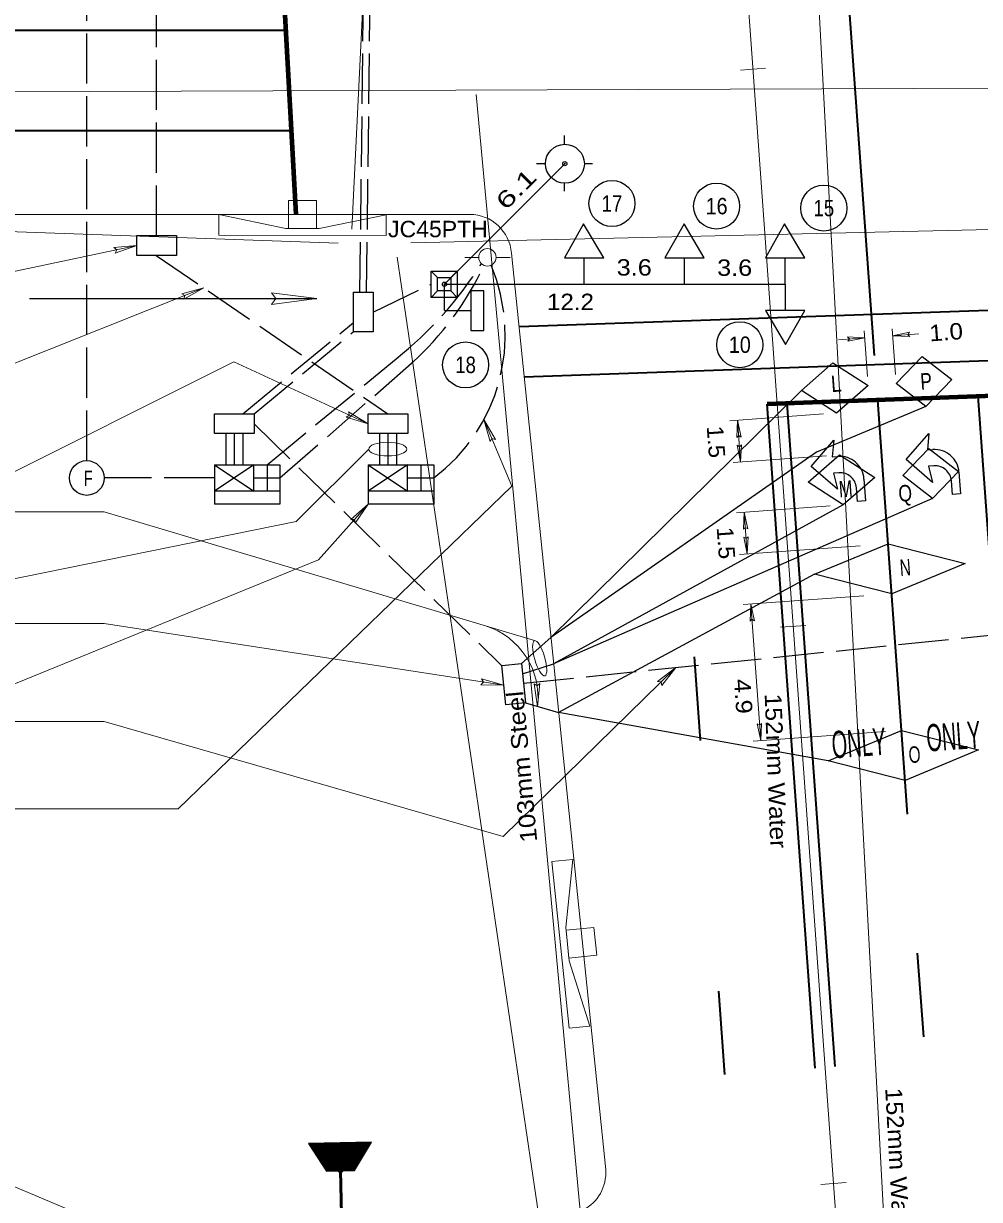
# Model space of a CAD drawing. Extents: x 168203 to 169863, y 223196 to 223870.
# Drawn here: x 168325.25 to 168359.48, y 223583.39 to 223625.5 of the extents above; entities that cross this region are included whole.
import ezdxf
from ezdxf.enums import TextEntityAlignment as Align

# ---------------------------------------------------------------- set-up
doc = ezdxf.new("R2010")
doc.units = 0
doc.header["$LTSCALE"] = 0.3
doc.header["$PDMODE"] = 32
doc.header["$PDSIZE"] = 0.15
doc.linetypes.add('LONG_DASH_SHORT_DASH', pattern=[9.9, 6, -1.2, 1.5, -1.2])
doc.linetypes.add('LONG_DASHED', pattern=[7.5, 6, -1.5])
for name, color, linetype, lineweight in [('1', 7, 'Continuous', 13), ('11', 7, 'Continuous', 13), ('23', 7, 'Continuous', 25), ('3', 7, 'Continuous', 25), ('31', 7, 'Continuous', 25), ('36', 7, 'Continuous', 35), ('5', 7, 'Continuous', 25), ('7', 7, 'Continuous', 25), ('9', 7, 'Continuous', 13)]:
    doc.layers.add(name, color=color, linetype=linetype, lineweight=lineweight)

msp = doc.modelspace()

# ---------------------------------------------------------------- linework, layer by layer
at = {"layer": '1'}
for p, q in [((168355.9956, 223559.8648), (168350.6186, 223634.2675)), ((168350.9207, 223623.8346), (168351.8184, 223623.8995)), ((168298.0344, 223618.6676), (168341.2267, 223618.6675)), ((168341.5495, 223617.1291), (168341.0495, 223617.1291)), ((168342.1745, 223617.1291), (168342.6745, 223617.1291)), ((168342.7229, 223617.2756), (168346.0972, 223584.4572)), ((168352.3629, 223603.8867), (168353.2606, 223603.9516)), ((168280.5516, 223602.5453), (168328.4093, 223582.3863)), ((168353.8048, 223583.9354), (168354.7025, 223584.0002))]:
    msp.add_line(p, q, dxfattribs=at)
for points in [[(168334.737, 223618.1634), (168334.737, 223619.1664), (168335.74, 223619.1664), (168335.74, 223618.1634)], [(168332.2417, 223618.6695), (168332.2401, 223617.9194), (168338.2401, 223617.9068), (168338.2417, 223618.6569), (168335.8406, 223618.1618), (168334.6406, 223618.1644)], [(168344.1749, 223595.4915), (168344.921, 223595.5682), (168344.6691, 223593.1297), (168344.7917, 223591.936), (168345.5347, 223589.5997), (168344.7885, 223589.523)], [(168344.6794, 223593.0358), (168345.6771, 223593.1383), (168345.7797, 223592.1406), (168344.782, 223592.038)]]:
    msp.add_lwpolyline(points, close=True, dxfattribs=at)
msp.add_circle((168341.862, 223617.1291), 0.3125, dxfattribs=at)
for centre, start, end in [((168341.2267, 223617.1675), 4.13349, 90.00005), ((168344.6012, 223584.3492), 297.10142, 4.13349)]:
    msp.add_arc(centre, 1.5, start, end, dxfattribs=at)
at = {"layer": '11'}
for p, q in [((168329.3071, 223617.5491), (168323.7837, 223616.3871)), ((168331.7086, 223616.0342), (168323.7837, 223612.8871)), ((168330.7837, 223597.3871), (168305.2886, 223597.3871))]:
    msp.add_line(p, q, dxfattribs=at)
for points in [[(168328.4908, 223617.4789), (168329.3071, 223617.5491), (168328.5335, 223617.2756), (168328.5909, 223617.3984)], [(168330.916, 223615.8264), (168331.7086, 223616.0342), (168330.9927, 223615.6333), (168331.0284, 223615.7641)], [(168336.8928, 223611.5991), (168337.5893, 223611.1675), (168336.8056, 223611.4104), (168336.925, 223611.4747)], [(168341.9597, 223610.5314), (168341.7389, 223611.3205), (168342.1515, 223610.6113), (168342.0201, 223610.6448)], [(168336.9737, 223607.7476), (168337.5888, 223608.2889), (168337.1289, 223607.6094), (168337.102, 223607.7423)]]:
    msp.add_lwpolyline(points, close=True, dxfattribs=at)
for points in [[(168337.5893, 223611.1675), (168332.7853, 223613.3888), (168323.7837, 223608.8871)], [(168341.7389, 223611.3205), (168342.7329, 223608.9324), (168330.7837, 223597.3871)], [(168337.6116, 223610.2636), (168335.0198, 223607.6653), (168323.7837, 223605.3871)], [(168337.5888, 223608.2889), (168335.8167, 223606.299), (168323.7837, 223601.3871)]]:
    msp.add_lwpolyline(points, dxfattribs=at)
msp.add_ellipse((168338.2938, 223610.2636), major_axis=(-0.6822, 0), ratio=0.356808, dxfattribs=at)
at = {"layer": '23', "lineweight": 13}
for p, q in [((168357.586, 223554.132), (168349.5897, 223703.4835)), ((168340.1403, 223682.8465), (168337.0072, 223618.1402)), ((168298.0362, 223622.959), (168427.4519, 223623.4301)), ((168347.1263, 223562.1814), (168341.4609, 223622.959)), ((168233.3078, 223621.2838), (168336.515, 223617.6326)), ((168339.1201, 223617.6451), (168427.4519, 223619.7026)), ((168348.0491, 223553.4435), (168338.6279, 223617.1375))]:
    msp.add_line(p, q, dxfattribs=at)
at = {"layer": '23'}
for p, q in [((168335.4735, 223585.375), (168337.6918, 223585.4203)), ((168335.4897, 223585.3503), (168337.6767, 223585.395)), ((168335.5057, 223585.3255), (168337.6615, 223585.3697)), ((168335.5219, 223585.3009), (168337.6465, 223585.3444)), ((168335.538, 223585.2762), (168337.6313, 223585.3191)), ((168335.5542, 223585.2515), (168337.6162, 223585.2937)), ((168335.5703, 223585.2269), (168337.6011, 223585.2684)), ((168335.5864, 223585.2022), (168337.586, 223585.2432)), ((168335.6025, 223585.1775), (168337.5709, 223585.2179)), ((168335.6188, 223585.1529), (168337.5558, 223585.1925)), ((168335.6348, 223585.1282), (168337.5407, 223585.1672)), ((168335.6509, 223585.1035), (168337.5256, 223585.1419)), ((168335.6671, 223585.0788), (168337.5104, 223585.1166)), ((168335.6832, 223585.0541), (168337.4953, 223585.0912)), ((168335.6994, 223585.0294), (168337.4802, 223585.0659)), ((168335.7155, 223585.0048), (168337.4651, 223585.0406)), ((168335.7316, 223584.9801), (168337.45, 223585.0153)), ((168335.7478, 223584.9554), (168337.435, 223584.99)), ((168335.7639, 223584.9308), (168337.4198, 223584.9646)), ((168335.78, 223584.9061), (168337.4047, 223584.9394)), ((168335.7961, 223584.8814), (168337.3895, 223584.9141)), ((168335.8123, 223584.8568), (168337.3745, 223584.8888)), ((168335.8284, 223584.8321), (168337.3593, 223584.8634)), ((168335.8446, 223584.8074), (168337.3442, 223584.8381)), ((168335.8606, 223584.7827), (168337.3291, 223584.8128)), ((168335.8769, 223584.758), (168337.3141, 223584.7875)), ((168335.893, 223584.7334), (168337.2989, 223584.7622)), ((168335.9091, 223584.7087), (168337.2838, 223584.7368)), ((168335.9252, 223584.684), (168337.2687, 223584.7115)), ((168335.9413, 223584.6594), (168337.2536, 223584.6862)), ((168335.9575, 223584.6347), (168337.2384, 223584.6609)), ((168335.9736, 223584.61), (168337.2233, 223584.6355)), ((168335.9897, 223584.5853), (168337.2083, 223584.6103)), ((168336.0059, 223584.5606), (168337.1932, 223584.585)), ((168336.0221, 223584.5359), (168337.178, 223584.5597)), ((168336.0381, 223584.5113), (168337.163, 223584.5343)), ((168336.0543, 223584.4866), (168337.1479, 223584.509)), ((168336.0705, 223584.4619), (168337.1327, 223584.4837)), ((168336.0866, 223584.4373), (168337.1175, 223584.4584))]:
    msp.add_line(p, q, dxfattribs=at)
at = {"layer": '23', "lineweight": 53}
msp.add_line((168336.8416, 223572.7261), (168336.6026, 223584.4228), dxfattribs=at)
at = {"layer": '23'}
msp.add_lwpolyline([(168336.1027, 223584.4126), (168337.1025, 223584.4331), (168337.7069, 223585.4457), (168335.4573, 223585.3996)], close=True, dxfattribs=at)
msp.add_point((168336.6026, 223584.4228), dxfattribs=at)
at = {"layer": '3'}
for p, q in [((168339.8448, 223616.6374), (168340.0797, 223616.4024)), ((168340.7845, 223616.6374), (168340.5496, 223616.4024)), ((168339.8448, 223615.6976), (168340.0797, 223615.9326)), ((168340.7845, 223615.6976), (168340.5496, 223615.9326))]:
    msp.add_line(p, q, dxfattribs=at)
for points in [[(168339.8448, 223616.6374), (168340.7845, 223616.6374), (168340.7845, 223615.6976), (168339.8448, 223615.6976)], [(168340.0797, 223616.4024), (168340.5496, 223616.4024), (168340.5496, 223615.9326), (168340.0797, 223615.9326)]]:
    msp.add_lwpolyline(points, close=True, dxfattribs=at)
msp.add_point((168340.3237, 223616.1675), dxfattribs=at)
at = {"layer": '31'}
for p, q in [((168340.3237, 223616.1675), (168344.6371, 223620.4809)), ((168345.3237, 223616.1675), (168345.3237, 223617.1073)), ((168348.9237, 223616.1675), (168348.9237, 223617.1073)), ((168352.5237, 223616.1675), (168352.5237, 223617.1073)), ((168340.3237, 223616.1675), (168352.5237, 223616.1675)), ((168340.3237, 223615.2277), (168340.3237, 223616.1675)), ((168352.5237, 223616.1675), (168352.5237, 223615.2277)), ((168340.3237, 223615.2277), (168341.2635, 223615.2277))]:
    msp.add_line(p, q, dxfattribs=at)
at = {"layer": '31', "linetype": 'LONG_DASH_SHORT_DASH'}
for points in [[(168345.3056, 223618.3271), (168344.6189, 223617.1073), (168345.3237, 223617.1073), (168346.0285, 223617.1073)], [(168348.9056, 223618.3271), (168348.2189, 223617.1073), (168348.9237, 223617.1073), (168349.6285, 223617.1073)], [(168352.5056, 223618.3271), (168351.8189, 223617.1073), (168352.5237, 223617.1073), (168353.2285, 223617.1073)], [(168341.7333, 223614.5138), (168341.7333, 223615.9325), (168341.2635, 223615.9325), (168341.2635, 223614.5138)], [(168352.5418, 223614.0079), (168353.2285, 223615.2277), (168352.5237, 223615.2277), (168351.8189, 223615.2277)]]:
    msp.add_lwpolyline(points, close=True, dxfattribs=at)
at = {"layer": '31'}
for centre in [(168346.3229, 223619.0571), (168350.0688, 223618.964), (168353.9078, 223618.8942), (168350.8998, 223614.0005), (168341.0797, 223613.279)]:
    msp.add_circle(centre, 0.8236, dxfattribs=at)
at = {"layer": '36', "lineweight": 80}
for p, q in [((168335.0149, 223618.6671), (168334.1789, 223633.9633)), ((168374.8667, 223612.7316), (168351.8768, 223611.872))]:
    msp.add_line(p, q, dxfattribs=at)
at = {"layer": '36'}
for p, q in [((168355.7208, 223613.6203), (168354.7732, 223626.7317)), ((168319.4575, 223625.267), (168334.6542, 223625.267)), ((168298.0351, 223621.6671), (168334.851, 223621.667)), ((168374.0279, 223615.7265), (168342.9941, 223614.6383)), ((168375.9373, 223613.9924), (168343.1786, 223612.8438)), ((168354.3131, 223588.1493), (168352.5967, 223611.8989)), ((168356.9077, 223597.1964), (168355.8364, 223612.0201)), ((168361.075, 223589.4767), (168359.4361, 223612.1546)), ((168353.5949, 223588.0975), (168351.8768, 223611.872)), ((168349.4984, 223599.8327), (168349.2822, 223602.8249)), ((168357.4843, 223589.2172), (168357.268, 223592.2094)), ((168350.3634, 223587.8639), (168350.1472, 223590.8561))]:
    msp.add_line(p, q, dxfattribs=at)
at = {"layer": '36', "linetype": 'LONG_DASH_SHORT_DASH', "lineweight": 25}
for points in [[(168357.8515, 223609.6633), (168357.6569, 223609.6492), (168357.7963, 223609.0726), (168356.8575, 223609.8848), (168357.6697, 223610.8236), (168357.6147, 223610.2329), (168357.8093, 223610.247)], [(168354.4494, 223609.4175), (168354.2548, 223609.4034), (168354.3942, 223608.8268), (168353.4554, 223609.639), (168354.2676, 223610.5778), (168354.2126, 223609.9871), (168354.4072, 223610.0012)], [(168358.7481, 223609.4347), (168358.8043, 223608.6565), (168358.5125, 223608.6354), (168358.4773, 223609.1218)], [(168355.346, 223609.1889), (168355.4022, 223608.4107), (168355.1104, 223608.3896), (168355.0752, 223608.876)]]:
    msp.add_lwpolyline(points, dxfattribs=at)
for centre, radius in [((168357.8725, 223609.3714), 0.8778), ((168354.4704, 223609.1256), 0.8778), ((168354.4915, 223608.8338), 0.5852), ((168357.8936, 223609.0796), 0.5852)]:
    msp.add_arc(centre, radius, 4.13419, 94.13419, dxfattribs=at)
at = {"layer": '5', "linetype": 'LONG_DASHED'}
for p, q in [((168337.299, 223615.8769), (168337.8409, 223661.0061)), ((168337.5361, 223615.8769), (168338.0771, 223660.9241)), ((168327.5151, 223609.8499), (168327.5152, 223654.5309)), ((168330.0164, 223617.906), (168330.0165, 223654.3632)), ((168330.0032, 223617.2012), (168338.2986, 223611.5244)), ((168337.7676, 223615.1676), (168339.8448, 223616.1675)), ((168333.1047, 223611.5244), (168337.0628, 223614.7965)), ((168333.505, 223611.5244), (168337.0538, 223614.4582)), ((168333.9743, 223609.6986), (168338.5949, 223613.5)), ((168334.4352, 223609.2287), (168339.1426, 223613.3344)), ((168333.505, 223611.1675), (168342.3722, 223602.515)), ((168332.5, 223610.8196), (168332.5, 223609.6986)), ((168332.7956, 223610.8196), (168332.7956, 223609.6986)), ((168333.0994, 223610.8196), (168333.0994, 223609.6986)), ((168338.003, 223610.8196), (168338.003, 223609.6986)), ((168338.2986, 223610.8196), (168338.2986, 223609.6986)), ((168338.6024, 223610.8196), (168338.6024, 223609.6986)), ((168332.0858, 223609.2287), (168328.1363, 223609.2287)), ((168343.1548, 223601.8824), (168372.8226, 223604.9326)), ((168343.0823, 223602.588), (168344.137, 223603.5217)), ((168343.1206, 223602.2151), (168344.2347, 223602.5721)), ((168343.2274, 223601.1767), (168344.4135, 223600.8327))]:
    msp.add_line(p, q, dxfattribs=at)
at = {"layer": '5', "lineweight": 13}
for p, q in [((168355.4744, 223612.8592), (168355.3562, 223614.4939)), ((168356.4725, 223612.9314), (168356.3543, 223614.5661)), ((168354.436, 223614.1804), (168355.374, 223614.2482)), ((168356.3721, 223614.3203), (168357.3101, 223614.3881)), ((168350.5485, 223611.2783), (168353.8961, 223611.5202)), ((168350.9293, 223609.8018), (168350.8212, 223611.2979)), ((168350.6566, 223609.7822), (168354.0042, 223610.0241)), ((168350.7863, 223607.9868), (168354.1339, 223608.2287)), ((168351.1671, 223606.5103), (168351.059, 223608.0065)), ((168350.8944, 223606.4906), (168355.2071, 223606.8023)), ((168351.0242, 223604.6952), (168355.3369, 223605.0069)), ((168351.6501, 223599.8276), (168351.2969, 223604.7149)), ((168351.3774, 223599.8079), (168356.1187, 223600.1506))]:
    msp.add_line(p, q, dxfattribs=at)
at = {"layer": '5'}
for p, q in [((168353.1038, 223612.3653), (168344.137, 223603.5217)), ((168332.0858, 223609.6986), (168333.4954, 223608.7588)), ((168333.4954, 223609.6986), (168332.0858, 223608.7588)), ((168332.0858, 223609.6986), (168334.4352, 223609.6986)), ((168332.0858, 223609.6986), (168332.0858, 223608.7588)), ((168333.4954, 223608.7588), (168333.4954, 223609.6986)), ((168333.9743, 223609.6986), (168333.9743, 223608.7588)), ((168334.4352, 223609.6986), (168334.4352, 223608.7588)), ((168337.5888, 223609.6986), (168338.9984, 223608.7588)), ((168338.9984, 223609.6986), (168337.5888, 223608.7588)), ((168337.5888, 223609.6986), (168339.9382, 223609.6986)), ((168337.5888, 223609.6986), (168337.5888, 223608.7588)), ((168338.9984, 223608.7588), (168338.9984, 223609.6986)), ((168339.4773, 223609.6986), (168339.4773, 223608.7588)), ((168339.9382, 223609.6986), (168339.9382, 223608.7588)), ((168333.4954, 223609.2287), (168334.4352, 223609.2287)), ((168338.9984, 223609.2287), (168339.9382, 223609.2287)), ((168334.4352, 223608.7588), (168332.0858, 223608.7588)), ((168332.0858, 223608.7588), (168332.0858, 223608.2889)), ((168334.4352, 223608.7588), (168334.4352, 223608.2889)), ((168339.9382, 223608.7588), (168337.5888, 223608.7588)), ((168337.5888, 223608.7588), (168337.5888, 223608.2889)), ((168339.9382, 223608.7588), (168339.9382, 223608.2889)), ((168334.4352, 223608.2889), (168332.0858, 223608.2889)), ((168339.9382, 223608.2889), (168337.5888, 223608.2889)), ((168357.7959, 223608.4933), (168344.2347, 223602.5721)), ((168354.6035, 223608.2625), (168344.2347, 223602.5721)), ((168353.5796, 223605.7823), (168344.4135, 223600.8327)), ((168354.0626, 223599.0996), (168344.4135, 223600.8327))]:
    msp.add_line(p, q, dxfattribs=at)
for points in [[(168330.7258, 223617.2012), (168329.3071, 223617.2012), (168329.3071, 223617.906), (168330.7258, 223617.906)], [(168337.7676, 223615.8769), (168337.7676, 223614.4582), (168337.0628, 223614.4582), (168337.0628, 223615.8769)], [(168356.4957, 223612.6104), (168357.4282, 223613.5802), (168358.4904, 223612.7546), (168357.558, 223611.7848)], [(168354.2359, 223613.3495), (168355.4976, 223612.5383), (168354.3656, 223611.5541), (168353.1038, 223612.3653)], [(168333.505, 223610.8196), (168332.0863, 223610.8196), (168332.0863, 223611.5244), (168333.505, 223611.5244)], [(168339.008, 223610.8196), (168337.5893, 223610.8196), (168337.5893, 223611.5244), (168339.008, 223611.5244)], [(168356.7336, 223609.3189), (168357.6661, 223610.2887), (168358.7283, 223609.4631), (168357.7959, 223608.4933)], [(168354.4738, 223610.0579), (168355.7355, 223609.2467), (168354.6035, 223608.2625), (168353.3417, 223609.0737)], [(168353.5796, 223605.7823), (168356.208, 223606.8746), (168358.9662, 223606.1716), (168356.3378, 223605.0792)], [(168342.5263, 223601.1047), (168342.3812, 223602.5159), (168343.0823, 223602.588), (168343.2274, 223601.1768)], [(168354.0626, 223599.0996), (168356.691, 223600.1919), (168359.4492, 223599.4889), (168356.8208, 223598.3965)]]:
    msp.add_lwpolyline(points, close=True, dxfattribs=at)
at = {"layer": '5', "lineweight": 13}
for points in [[(168356.9858, 223614.2899), (168356.3721, 223614.3203), (168356.9746, 223614.4453), (168356.9196, 223614.3598)], [(168354.7603, 223614.2786), (168355.374, 223614.2482), (168354.7715, 223614.1232), (168354.8265, 223614.2087)], [(168350.7908, 223610.6842), (168350.8212, 223611.2979), (168350.9462, 223610.6954), (168350.8607, 223610.7504)], [(168350.9597, 223610.4155), (168350.9293, 223609.8018), (168350.8043, 223610.4043), (168350.8898, 223610.3493)], [(168351.0286, 223607.3928), (168351.059, 223608.0065), (168351.184, 223607.404), (168351.0985, 223607.459)], [(168351.1975, 223607.124), (168351.1671, 223606.5103), (168351.0421, 223607.1128), (168351.1276, 223607.0578)], [(168351.2665, 223604.1012), (168351.2969, 223604.7149), (168351.4219, 223604.1124), (168351.3364, 223604.1674)], [(168351.6805, 223600.4413), (168351.6501, 223599.8276), (168351.5251, 223600.4301), (168351.6106, 223600.3751)]]:
    msp.add_lwpolyline(points, close=True, dxfattribs=at)
at = {"layer": '5'}
msp.add_lwpolyline([(168357.558, 223611.7848), (168353.6504, 223610.157), (168344.137, 223603.5217)], dxfattribs=at)
msp.add_circle((168327.5151, 223609.2287), 0.6212, dxfattribs=at)
at = {"layer": '5', "linetype": 'LONG_DASHED'}
for centre, radius, start, end in [((168330.2654, 223624.0427), 13.4361, 308.31148, 327.89744), ((168331.9487, 223621.3616), 10.779, 311.86635, 335.21891), ((168336.1096, 223614.3454), 6.3906, 306.80597, 23.02086)]:
    msp.add_arc(centre, radius, start, end, dxfattribs=at)
at = {"layer": '7'}
for p, q in [((168344.6211, 223621.1741), (168344.6275, 223621.4873)), ((168343.6243, 223620.4841), (168343.9438, 223620.4841)), ((168345.3368, 223620.4841), (168345.6243, 223620.4904)), ((168344.6276, 223619.4937), (168344.6212, 223619.7812))]:
    msp.add_line(p, q, dxfattribs=at)
msp.add_circle((168344.6371, 223620.4809), 0.6965, dxfattribs=at)
msp.add_point((168344.6339, 223620.4841), dxfattribs=at)
at = {"layer": '9', "lineweight": 25}
msp.add_line((168325.472, 223615.6542), (168335.7557, 223615.6542), dxfattribs=at)
at = {"layer": '9'}
for p, q in [((168328.1441, 223608.0135), (168304.2706, 223608.0135)), ((168343.5506, 223603.4058), (168328.1441, 223608.0135)), ((168328.1441, 223604.0135), (168304.2706, 223604.0135)), ((168342.4448, 223601.8094), (168328.1441, 223604.0135)), ((168328.1441, 223600.5135), (168304.2706, 223600.5135))]:
    msp.add_line(p, q, dxfattribs=at)
for points in [[(168334.1291, 223615.853), (168335.7557, 223615.6542), (168334.1291, 223615.4374), (168334.2919, 223615.6542)], [(168347.9575, 223601.9456), (168348.6085, 223602.4431), (168348.1028, 223601.797), (168348.0852, 223601.9314)], [(168341.6561, 223602.0315), (168342.4448, 223601.8094), (168341.6245, 223601.8262), (168341.7214, 223601.9209)], [(168343.744, 223601.8665), (168343.659, 223601.0515), (168343.5363, 223601.8628), (168343.6461, 223601.7833)]]:
    msp.add_lwpolyline(points, close=True, dxfattribs=at)
msp.add_lwpolyline([(168348.6085, 223602.4431), (168342.4242, 223596.3958), (168328.1441, 223600.5135)], dxfattribs=at)
msp.add_arc((168340.9894, 223601.3663), 2.6881, 353.27499, 72.67074, dxfattribs=at)
msp.add_ellipse((168343.7344, 223602.7761), major_axis=(-0.1838, 0.6297), ratio=0.276966, dxfattribs=at)

# ---------------------------------------------------------------- texts
at = {"layer": '1', "width": 1.05}
msp.add_text('JC45PTH', height=0.5873, dxfattribs=at).set_placement((168340.0912, 223617.8497), align=Align.CENTER)
at = {"layer": '23'}
for s, rotation, width, p in [('103mm Steel', 95.325, 1.15, (168343.3953, 223598.9155)), ('152mm Water', 272.144, 1.1, (168351.8933, 223598.7263)), ('152mm Water', 273.065, 1.1, (168356.2546, 223584.6096))]:
    msp.add_text(s, height=0.6, rotation=rotation, dxfattribs=dict(at, width=width)).set_placement(p, align=Align.CENTER)
at = {"layer": '31', "width": 1.5}
msp.add_text('6.1', height=0.5873, rotation=45, dxfattribs=at).set_placement((168343.0984, 223619.3665), align=Align.CENTER)
at = {"layer": '31'}
for s, width, p in [('17', 0.85, (168346.3228, 223618.7635)), ('16', 0.9, (168350.0688, 223618.6704)), ('15', 0.85, (168353.9078, 223618.6006)), ('3.6', 1.15, (168347.1205, 223616.4771)), ('3.6', 1.15, (168350.7153, 223616.4675)), ('12.2', 1.1, (168344.8363, 223615.2411)), ('10', 0.9, (168350.8998, 223613.7069)), ('18', 0.85, (168341.0796, 223612.9854))]:
    msp.add_text(s, height=0.5873, dxfattribs=dict(at, width=width)).set_placement(p, align=Align.CENTER)
at = {"layer": '36', "width": 0.55}
for p in [(168358.5823, 223599.4982), (168355.1935, 223599.2539)]:
    msp.add_text('ONLY', height=0.9715, rotation=3.898, dxfattribs=at).set_placement(p, align=Align.CENTER)
at = {"layer": '5'}
for s, rotation, width, p in [('1.0', 4.132, 1.1, (168358.3089, 223614.1625)), ('L', 4.134, 0.85, (168354.3719, 223612.3153)), ('P', 4.134, 0.8, (168357.5919, 223612.4003)), ('1.5', 274.133, 1.05, (168349.7562, 223610.5004)), ('M', 4.134, 0.75, (168354.7115, 223608.5469)), ('Q', 4.134, 0.8, (168356.8431, 223608.3925)), ('1.5', 274.132, 1.05, (168350.1129, 223606.8792)), ('N', 4.134, 0.7, (168356.8463, 223605.7326)), ('4.9', 274.134, 1.15, (168350.7326, 223601.391)), ('O', 4.134, 0.7, (168357.1773, 223599.032))]:
    msp.add_text(s, height=0.5873, rotation=rotation, dxfattribs=dict(at, width=width)).set_placement(p, align=Align.CENTER)
at = {"layer": '5', "width": 0.7}
msp.add_text('F', height=0.5506, dxfattribs=at).set_placement((168327.4157, 223608.9395))

doc.saveas('drawing.dxf')
